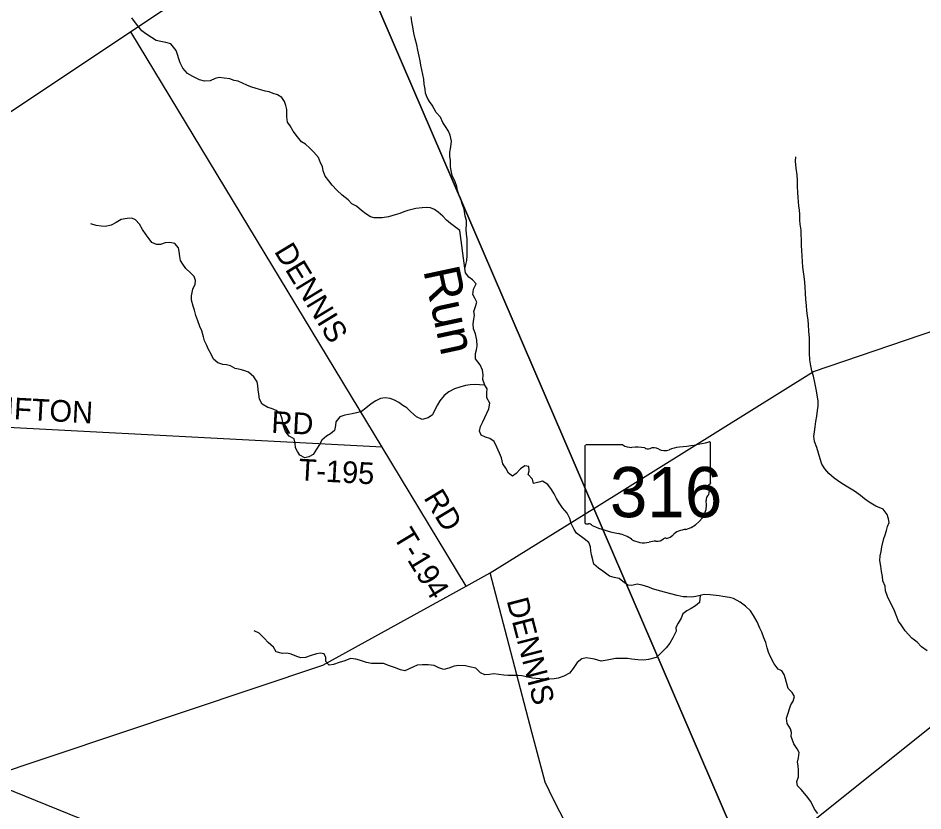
# Model space of a CAD drawing. Extents: x 1643459 to 2064572, y 425441 to 780708.
# Drawn here: x 1777506 to 1790021, y 609995 to 620966 of the extents above; entities that cross this region are included whole.
import ezdxf

# ---------------------------------------------------------------- set-up
doc = ezdxf.new("R2010")
doc.units = 0
for name, color, linetype in [('GM_X_City_Street', 7, 'Continuous'), ('GM_X_Interchange_Ramps', 7, 'Continuous'), ('GM_X_Major_River', 7, 'Continuous'), ('GM_X_Major_River_Text', 7, 'Continuous'), ('GM_X_US_Route', 7, 'Continuous'), ('PM_P_Cells', 7, 'Continuous'), ('RD_X_Text', 7, 'Continuous'), ('ST_Details', 7, 'Continuous')]:
    doc.layers.add(name, color=color, linetype=linetype)

msp = doc.modelspace()

# ---------------------------------------------------------------- linework, layer by layer
at = {"layer": 'GM_X_City_Street'}
for points in [[(1790575, 602316), (1789055, 605851), (1787632, 609158), (1785470, 614182), (1781837, 622626), (1781545, 623306), (1780359, 626159), (1779143, 629082), (1778092, 631612), (1783242, 631666), (1788081, 631718), (1790269, 631741)], [(1755032, 592905), (1755763, 604727), (1756758, 618359), (1756763, 618445), (1757178, 624925), (1758715, 624823), (1771965, 623943), (1775923, 623680), (1781545, 623306), (1781837, 622626), (1785470, 614182), (1787632, 609158), (1789055, 605851), (1790575, 602316), (1791118, 601055), (1793558, 602184), (1795084, 602890), (1794631, 595981)]]:
    msp.add_lwpolyline(points, dxfattribs=at)
at = {"layer": 'GM_X_Major_River_Text'}
for points in [[(1781934, 622690), (1781837, 622626), (1781604, 622471), (1781160, 622171), (1779067, 620775), (1773925, 617348)], [(1783705, 613106), (1782541, 615030), (1779067, 620775)], [(1782541, 615030), (1775340, 615408), (1774969, 615428)], [(1786073, 607913), (1784935, 610109), (1784851, 610278), (1784798, 610393), (1784611, 611086), (1784037, 613289)], [(1795915, 613058), (1792574, 611960), (1790565, 611342), (1790354, 611280), (1790302, 611265), (1790280, 611255), (1790228, 611231), (1787681, 609197)]]:
    msp.add_lwpolyline(points, dxfattribs=at)
at = {"layer": 'GM_X_US_Route'}
for points in [[(1783687, 617504), (1783617, 618027), (1783541, 618083), (1783487, 618124), (1783433, 618172), (1783379, 618223), (1783318, 618279), (1783266, 618316), (1783210, 618340), (1783160, 618345), (1783094, 618341), (1783007, 618331), (1782897, 618304), (1782840, 618284), (1782788, 618264), (1782720, 618242), (1782631, 618217), (1782541, 618201), (1782489, 618200), (1782431, 618202), (1782381, 618218), (1782317, 618259), (1782255, 618305), (1782187, 618362), (1782123, 618398), (1782070, 618451), (1781990, 618514), (1781916, 618586), (1781851, 618653), (1781803, 618713), (1781755, 618778), (1781724, 618852), (1781716, 618911), (1781690, 618963), (1781659, 619035), (1781591, 619114), (1781543, 619165), (1781482, 619221), (1781428, 619252), (1781372, 619322), (1781311, 619399), (1781269, 619473), (1781231, 619528), (1781222, 619600), (1781224, 619700), (1781211, 619755), (1781189, 619813), (1781155, 619869), (1781096, 619902), (1781036, 619924), (1780978, 619947), (1780923, 619957), (1780863, 619973), (1780801, 619990), (1780727, 620014), (1780669, 620039), (1780609, 620065), (1780552, 620094), (1780495, 620104), (1780433, 620126), (1780357, 620137), (1780289, 620143), (1780231, 620129), (1780163, 620100), (1780086, 620094), (1780014, 620111), (1779924, 620159), (1779848, 620200), (1779783, 620274), (1779747, 620345), (1779728, 620403), (1779712, 620464), (1779694, 620518), (1779617, 620611), (1779549, 620629), (1779481, 620642), (1779417, 620658), (1779353, 620696), (1779273, 620749), (1779219, 620790), (1779163, 620860), (1779116, 620917), (1779080, 620969)], [(1783687, 617504), (1783699, 617554), (1783714, 617613), (1783716, 617679), (1783717, 617791), (1783716, 617858), (1783716, 617910), (1783709, 617978), (1783705, 618044), (1783707, 618115), (1783706, 618167), (1783692, 618225), (1783677, 618320), (1783649, 618398), (1783630, 618464), (1783602, 618527), (1783584, 618581), (1783573, 618635), (1783553, 618698), (1783512, 618788), (1783496, 618855), (1783489, 618909), (1783487, 618995), (1783480, 619054), (1783478, 619112), (1783490, 619184), (1783501, 619264), (1783484, 619345), (1783458, 619401), (1783416, 619466), (1783383, 619520), (1783347, 619597), (1783287, 619659), (1783232, 619760), (1783198, 619810), (1783163, 619867), (1783141, 619929), (1783135, 619983), (1783122, 620050), (1783116, 620120), (1783091, 620250), (1783077, 620315), (1783068, 620375), (1783052, 620439), (1783035, 620522), (1783023, 620598), (1782998, 620681), (1782982, 620759), (1782967, 620843), (1782953, 620912), (1782944, 620988)], [(1789469, 613181), (1789461, 613239), (1789448, 613308), (1789438, 613380), (1789425, 613458), (1789431, 613523), (1789444, 613583), (1789452, 613651), (1789481, 613763), (1789498, 613816), (1789518, 613876), (1789532, 613930), (1789555, 613984), (1789547, 614038), (1789528, 614099), (1789472, 614171), (1789370, 614214), (1789276, 614269), (1789212, 614315), (1789157, 614360), (1789077, 614418), (1788961, 614491), (1788887, 614534), (1788795, 614599), (1788722, 614665), (1788664, 614728), (1788624, 614794), (1788599, 614867), (1788577, 614945), (1788552, 615022), (1788524, 615108), (1788513, 615181), (1788521, 615239), (1788532, 615311), (1788542, 615385), (1788553, 615456), (1788565, 615538), (1788574, 615594), (1788572, 615664), (1788565, 615725), (1788547, 615833), (1788528, 615924), (1788509, 616010), (1788487, 616085), (1788472, 616155), (1788458, 616239), (1788451, 616330), (1788452, 616535), (1788445, 616633), (1788438, 616725), (1788434, 616786), (1788426, 616846), (1788417, 616916), (1788411, 616989), (1788404, 617073), (1788397, 617161), (1788391, 617242), (1788388, 617314), (1788380, 617390), (1788369, 617455), (1788361, 617521), (1788358, 617595), (1788350, 617676), (1788345, 617752), (1788341, 617820), (1788342, 617893), (1788336, 617977), (1788335, 618031), (1788325, 618116), (1788321, 618172), (1788320, 618242), (1788312, 618311), (1788307, 618363), (1788301, 618427), (1788294, 618485), (1788292, 618552), (1788287, 618636), (1788285, 618718), (1788280, 618797), (1788268, 618891), (1788261, 618988), (1788262, 619048)], [(1779475, 617834), (1779421, 617831), (1779357, 617861), (1779317, 617912), (1779277, 617966), (1779226, 618039), (1779184, 618113), (1779130, 618174), (1779078, 618196), (1779016, 618194), (1778932, 618177), (1778861, 618139), (1778793, 618101), (1778717, 618084), (1778656, 618086), (1778584, 618098), (1778514, 618119)], [(1783964, 615886), (1783890, 615893), (1783836, 615895), (1783760, 615893), (1783696, 615884), (1783617, 615860), (1783543, 615834), (1783464, 615794), (1783400, 615743), (1783339, 615669), (1783309, 615615), (1783268, 615547), (1783238, 615478), (1783177, 615433), (1783093, 615413), (1783017, 615449), (1782937, 615518), (1782885, 615571), (1782827, 615605), (1782774, 615648), (1782712, 615678), (1782654, 615700), (1782582, 615713), (1782517, 615703), (1782453, 615669), (1782389, 615630), (1782318, 615570), (1782257, 615522), (1782187, 615502), (1782125, 615488), (1782027, 615471), (1781956, 615449), (1781902, 615379), (1781897, 615327), (1781881, 615259), (1781828, 615215), (1781772, 615179), (1781709, 615125), (1781673, 615067), (1781634, 615003), (1781586, 614929), (1781529, 614895), (1781473, 614880), (1781403, 614916), (1781369, 614968), (1781344, 615021), (1781340, 615083), (1781324, 615145), (1781257, 615182), (1781205, 615244), (1781179, 615317), (1781168, 615369), (1781158, 615419), (1781134, 615486), (1781075, 615536), (1781011, 615565), (1780961, 615579), (1780881, 615624), (1780847, 615694), (1780834, 615763), (1780828, 615821), (1780824, 615881), (1780811, 615933), (1780769, 616004), (1780695, 616067), (1780629, 616091), (1780577, 616101), (1780509, 616118), (1780445, 616156), (1780389, 616169), (1780337, 616173), (1780269, 616197), (1780209, 616248), (1780176, 616314), (1780136, 616387), (1780117, 616437), (1780085, 616500), (1780069, 616554), (1780046, 616638), (1780020, 616697), (1779993, 616775), (1779965, 616852), (1779944, 616924), (1779926, 616980), (1779906, 617063), (1779903, 617121), (1779922, 617215), (1779954, 617284), (1779962, 617334), (1779943, 617388), (1779893, 617441), (1779827, 617499), (1779784, 617560), (1779752, 617610), (1779744, 617666), (1779733, 617735), (1779723, 617789), (1779675, 617845), (1779605, 617862), (1779539, 617854), (1779475, 617834)], [(1787344, 612950), (1787254, 612964), (1787204, 612970), (1787078, 612985), (1786997, 612990), (1786939, 612974), (1786881, 612962), (1786825, 612954), (1786757, 612959), (1786707, 612959), (1786622, 612976), (1786534, 612998), (1786448, 613021), (1786396, 613037), (1786280, 613068), (1786228, 613092), (1786136, 613117), (1786068, 613133), (1785994, 613114), (1785940, 613118), (1785872, 613169), (1785818, 613213), (1785752, 613223), (1785688, 613242), (1785596, 613311), (1785532, 613355), (1785469, 613410), (1785457, 613468), (1785437, 613540), (1785430, 613595), (1785424, 613649), (1785399, 613711), (1785335, 613760), (1785231, 613837), (1785197, 613887), (1785156, 613970), (1785136, 614042), (1785099, 614113), (1785035, 614189), (1784991, 614258), (1784954, 614320), (1784920, 614381), (1784882, 614441), (1784831, 614510), (1784761, 614556), (1784711, 614543), (1784636, 614527), (1784619, 614585), (1784561, 614648), (1784577, 614700), (1784572, 614762), (1784514, 614771), (1784453, 614729), (1784397, 614663), (1784344, 614627), (1784291, 614671), (1784251, 614736), (1784213, 614798), (1784192, 614883), (1784166, 614947), (1784127, 615030), (1784089, 615106), (1784033, 615149), (1783969, 615167), (1783913, 615194), (1783890, 615248), (1783902, 615314), (1783933, 615378), (1783961, 615438), (1783988, 615498), (1784016, 615559), (1784033, 615637), (1783991, 615713), (1783988, 615782), (1783996, 615834), (1783964, 615886), (1783935, 615967), (1783941, 616031), (1783928, 616095), (1783896, 616170), (1783831, 616250), (1783831, 616325), (1783846, 616377), (1783854, 616433), (1783852, 616511), (1783835, 616598), (1783803, 616666), (1783800, 616735), (1783812, 616799), (1783821, 616855), (1783811, 616907), (1783834, 616973), (1783852, 617033), (1783825, 617092), (1783795, 617142), (1783807, 617214), (1783844, 617287), (1783792, 617343), (1783740, 617382), (1783693, 617442), (1783687, 617504)], [(1790082, 612208), (1790002, 612266), (1789940, 612329), (1789868, 612386), (1789777, 612487), (1789721, 612569), (1789684, 612622), (1789652, 612706), (1789626, 612765), (1789595, 612833), (1789563, 612893), (1789530, 612964), (1789506, 613042), (1789497, 613107), (1789469, 613181)], [(1786939, 612974), (1786933, 612878), (1786878, 612834), (1786818, 612796), (1786755, 612764), (1786699, 612720), (1786676, 612660), (1786634, 612594), (1786605, 612534), (1786607, 612484), (1786560, 612388), (1786520, 612318), (1786471, 612250), (1786382, 612164), (1786332, 612118), (1786225, 612088), (1786155, 612083), (1786077, 612085), (1785993, 612096), (1785935, 612102), (1785852, 612106), (1785770, 612103), (1785656, 612083), (1785573, 612068), (1785479, 612096), (1785423, 612105), (1785365, 612113), (1785305, 612101), (1785238, 612049), (1785184, 611967), (1785131, 611903), (1785055, 611858), (1784974, 611832), (1784922, 611824), (1784796, 611819), (1784723, 611821), (1784623, 611830), (1784561, 611846), (1784473, 611865), (1784419, 611871), (1784345, 611870), (1784281, 611870), (1784225, 611872), (1784156, 611881), (1784086, 611891), (1784028, 611881), (1783962, 611876), (1783902, 611908), (1783836, 611971), (1783750, 611991), (1783694, 612002), (1783602, 612008), (1783536, 611996), (1783465, 611969), (1783395, 611951), (1783327, 611976), (1783263, 612006), (1783177, 612015), (1783099, 612017), (1783027, 612013), (1782968, 611982), (1782856, 611932), (1782794, 611948), (1782714, 611981), (1782644, 612003), (1782560, 612036), (1782469, 612034), (1782393, 612033), (1782327, 612049), (1782229, 612080), (1782177, 612096), (1782105, 612105), (1782026, 612071), (1781946, 612049), (1781870, 612020), (1781810, 612014), (1781764, 612064), (1781762, 612119), (1781740, 612171), (1781682, 612179), (1781632, 612168), (1781546, 612140), (1781481, 612116), (1781417, 612115), (1781361, 612131), (1781283, 612163), (1781225, 612176), (1781163, 612174), (1781075, 612197), (1781037, 612261), (1780966, 612326), (1780916, 612382), (1780842, 612453), (1780770, 612488)], [(1788566, 609957), (1788524, 610017), (1788473, 610124), (1788409, 610205), (1788336, 610290), (1788286, 610344), (1788276, 610400), (1788301, 610468), (1788302, 610557), (1788296, 610617), (1788286, 610669), (1788299, 610731), (1788311, 610804), (1788284, 610856), (1788234, 610925), (1788199, 611027), (1788205, 611079), (1788191, 611132), (1788142, 611206), (1788136, 611279), (1788159, 611347), (1788175, 611409), (1788194, 611463), (1788228, 611515), (1788245, 611577), (1788213, 611634), (1788157, 611690), (1788134, 611773), (1788122, 611825), (1788102, 611883), (1788069, 611934), (1788017, 611956), (1787963, 612029), (1787910, 612137), (1787886, 612190), (1787868, 612252), (1787847, 612324), (1787823, 612391), (1787794, 612469), (1787764, 612526), (1787727, 612612), (1787677, 612699), (1787635, 612763), (1787568, 612830), (1787494, 612885), (1787400, 612935), (1787344, 612950)]]:
    msp.add_lwpolyline(points, dxfattribs=at)
at = {"layer": 'RD_X_Text'}
for points in [[(1777021, 610437), (1781723, 612013), (1783705, 613106), (1784037, 613289), (1785470, 614182), (1788508, 616074), (1793844, 617891)], [(1776024, 610826), (1777021, 610437), (1777301, 610324), (1780885, 608867), (1781769, 608388), (1782581, 608065), (1783790, 607688), (1784085, 607562), (1784931, 607037), (1785328, 606791), (1785462, 606705), (1786867, 606458), (1787694, 606306), (1789055, 605851), (1790576, 605545), (1791756, 605204)]]:
    msp.add_lwpolyline(points, dxfattribs=at)
at = {"layer": 'ST_Details'}
for p, q in [((1785344, 615041), (1785344, 613984)), ((1785871, 615059), (1785362, 615059)), ((1787085, 614532), (1787085, 615085)), ((1787084, 614533), (1787085, 614532))]:
    msp.add_line(p, q, dxfattribs=at)
for centre, major_axis, start_param, end_param in [((1785364, 615043), (20.2, 0), 1.712693, 3.28349), ((1785993, 615182), (196, 0), 4.042523, 4.731795), ((1786057, 614466), (702, 0), 1.404758, 1.657858), ((1786217, 615049), (56.4, 0), 3.836095, 5.185415), ((1786300, 614926), (117, 0), 0.950623, 2.079405), ((1786451, 615094), (141, 0), 4.081561, 5.145723), ((1786700, 614736), (371, 0), 1.699011, 2.107814), ((1786465, 616500), (1845, 0), 4.814394, 5.042369), ((1787065, 615087), (19.4, 0), 6.141152, 7.989035), ((1787080, 614492), (30, 0), 1.883978, 3.671073), ((1787064, 614530), (20.7, 0), 5.05454, 6.418171), ((1787154, 614301), (131, 0), 2.387724, 3.262537), ((1786889, 614422), (180, 0), 5.934695, 6.695948), ((1786568, 614231), (462, 0), 5.101752, 6.440018), ((1785365, 613982), (20.3, 0), 3.00124, 4.508301), ((1785368, 614090), (155, 0), 4.665946, 4.897461), ((1785399, 613923), (56, 0), 0.519207, 1.627899), ((1786106, 614873), (1333, 0), 4.195997, 4.488961), ((1786763, 613688), (253, 0), 1.647645, 2.488434), ((1785709, 613509), (417, 0), 0.823519, 1.323587), ((1786160, 613918), (265, 0), 4.026481, 4.996735), ((1786332, 613839), (141, 0), 4.691044, 5.507374), ((1786459, 613736), (39.7, 0), 1.147584, 2.315152), ((1786442, 613882), (149, 0), 4.937069, 5.64225), ((1786313, 613553), (217, 0), 1.495662, 1.94098)]:
    msp.add_ellipse(centre, major_axis=major_axis, ratio=0.8, start_param=start_param, end_param=end_param, dxfattribs=at)

# ---------------------------------------------------------------- texts
at = {"layer": 'GM_X_Interchange_Ramps'}
msp.add_text('Run', height=500.1, rotation=282.1116, dxfattribs=at).set_placement((1783109, 617475))
at = {"layer": 'GM_X_Major_River'}
for s, rotation, p in [('DENNIS', 301.2527, (1781041, 617738)), ('CLIFTON', 356.9102, (1776820, 615449)), ('RD', 357.0407, (1781004, 615229)), ('T-195', 356.8979, (1781379, 614570)), ('RD', 301.2192, (1783109, 614328)), ('T-194', 301.2038, (1782686, 613795)), ('DENNIS', 284.5344, (1784262, 612906))]:
    msp.add_text(s, height=300, rotation=rotation, dxfattribs=at).set_placement(p)
at = {"layer": 'PM_P_Cells'}
msp.add_text('316', height=1, rotation=0, dxfattribs=at).set_placement((1785842, 614369))
for s in ['s', 'r']:
    msp.add_text(s, height=1, dxfattribs=at).set_placement((1786195, 614442))
at = {"layer": 'ST_Details'}
msp.add_text('316', height=696.1, dxfattribs=at).set_placement((1785692, 614059))

doc.saveas('drawing.dxf')
